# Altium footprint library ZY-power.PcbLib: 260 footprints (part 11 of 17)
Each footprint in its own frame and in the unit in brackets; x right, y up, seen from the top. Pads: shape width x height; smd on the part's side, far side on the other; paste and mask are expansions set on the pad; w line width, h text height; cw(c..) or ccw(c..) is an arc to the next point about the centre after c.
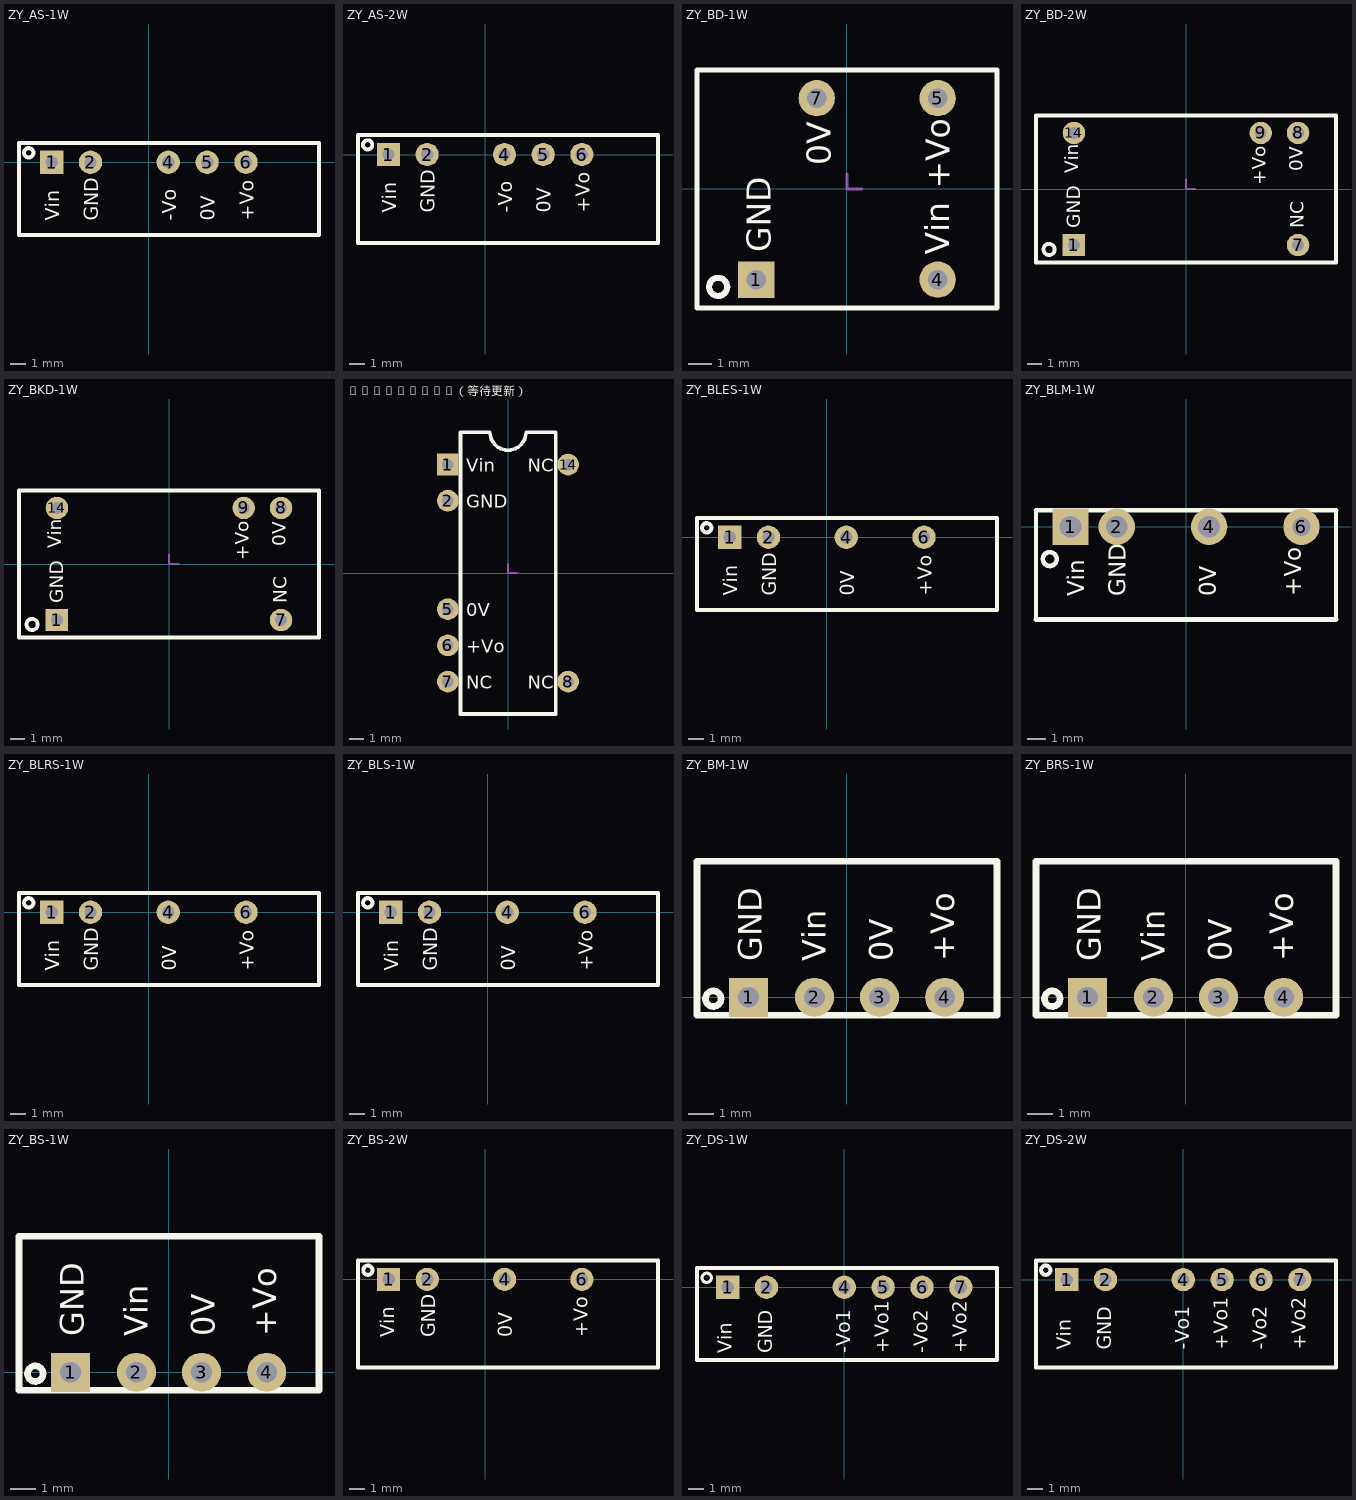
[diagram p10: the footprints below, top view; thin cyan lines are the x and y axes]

## ZY_AS-1W [mil] "定压输入隔离非稳压正、负双输出"
height 393.7
pads (5):
  rect 60x60 hole 32: 1(-250,0)
  round 60 hole 32: 2(-150,0) 4(50,0) 5(150,0) 6(250,0)
Top Overlay:
  circle w10: c-308.86,24.21 r12
  lines w10: -333.86,-187.01 -333.86,49.21 437.8,49.21 437.8,-187.01 -333.86,-187.01
  text "+Vo" at 270,-150 h36
  text "0V" at 170,-150 h36
  text "GND" at -130,-150 h36
  text "Vin" at -230,-150 h36
  text "-Vo" at 70,-150 h36

## ZY_AS-2W [mil] "定压输入隔离非稳压正、负双输出"
height 393.7
pads (5):
  rect 60x60 hole 32: 1(-250,0)
  round 60 hole 32: 2(-150,0) 4(50,0) 5(150,0) 6(250,0)
Top Overlay:
  circle w10: c-303.74,25 r12
  lines w10: 442.91,-228.35 -328.74,-228.35 -328.74,50 -303.74,50 ; 446.85,-228.35 446.85,49.21 ; 446.85,50 -300,50 ; -303.74,50 -300,50 ; -303.74,50 -300,50
  text "+Vo" at 270,-150 h36
  text "0V" at 170,-150 h36
  text "GND" at -130,-150 h36
  text "Vin" at -230,-150 h36
  text "-Vo" at 70,-150 h36

## ZY_BD-1W [mil] "定压输入隔离非稳压单输出"
height 303.15
pads (4):
  rect 60x60 hole 32: 1(-150,-150)
  round 60 hole 32: 4(150,-150) 5(150,150) 7(-50,150)
Top Overlay:
  circle w10: c-213,-162 r15
  lines w8: -248,-197 248.06,-197 248.06,196.7 -248,196.7 -248,-197
  text "0V" at -27,39 h40
  text "+Vo" at 170,0 h40
  text "Vin" at 169,-109 h40
  text "GND" at -126,-105 h40
Mechanical 15:
  lines w5: 0,25 0,0 25,0

## ZY_BD-2W [mil]
height 318.9
pads (5):
  rect 60x60 hole 31.5: 1(-300,-150)
  round 60 hole 31.5: 7(300,-150) 8(300,150) 9(200,150) 14(-300,150)
Top Overlay:
  circle w10: c-366.57,-161.85 r15
  lines w10: -401.57,-196.85 401.57,-196.85 401.57,196.85 -401.57,196.85 -401.57,-196.85
  text "0V" at 312,47 h36
  text "+Vo" at 214,10.66 h36
  text "Vin" at -288,42.37 h36
  text "NC" at 315,-105 h36
  text "GND" at -283,-105 h36
Mechanical 15:
  lines w5: 0,25 0,0 25,0

## ZY_BKD-1W [mil]
height 318.9
pads (5):
  rect 60x60 hole 31.5: 1(-300,-150)
  round 60 hole 31.5: 7(300,-150) 8(300,150) 9(200,150) 14(-300,150)
Top Overlay:
  circle w10: c-366.57,-161.85 r15
  lines w10: -401.57,-196.85 -401.57,196.85 401.57,196.85 401.57,-196.85 -401.57,-196.85
  text "GND" at -283,-105 h36
  text "NC" at 315,-105 h36
  text "Vin" at -288,42.37 h36
  text "+Vo" at 214,10.66 h36
  text "0V" at 312,47 h36
Mechanical 15:
  lines w5: 0,25 0,0 25,0

## ZY_BLD-1W（等待更新） [mil] "定压输入隔离非稳压单输出"
height 216.54
pads (7):
  rect 60x60 hole 32: 1(-166.34,300)
  round 60 hole 32: 2(-166.34,200) 5(-166.34,-100) 6(-166.34,-200) 7(-166.34,-300) 8(166.34,-300) 14(166.34,300)
Top Overlay:
  lines w10: -131.34,-389.76 -131.34,389.76 -50,389.76 ccw(c0,389.76) 0,339.76 ccw(c0,389.76) 50,389.76 131.66,389.76 131.66,-389.76 -131.34,-389.76
  text "NC" at 55,280 h36
  text "NC" at 55,-320 h36
  text "NC" at -115,-320 h36
  text "0V" at -115,-120 h36
  text "+Vo" at -115,-220 h36
  text "GND" at -115,180 h36
  text "Vin" at -115,280 h36
Mechanical 15:
  lines w5: 0,25 0,0 25,0

## ZY_BLES-1W [mil]
height 393.7
pads (4):
  rect 60x60 hole 32: 1(-250,0)
  round 60 hole 32: 2(-150,0) 4(50,0) 6(250,0)
Top Overlay:
  circle w10: c-308.86,24.21 r12
  lines w10: -333.86,-187.01 -333.86,49.21 437.8,49.21 437.8,-187.01 -333.86,-187.01
  text "+Vo" at 270,-150 h36
  text "0V" at 71,-150 h36
  text "GND" at -130,-150 h36
  text "Vin" at -230,-150 h36

## ZY_BLM-1W [mm]
height 7.5
pads (4):
  rect 2x2 hole 1.2: 1(-6.35,0)
  round 2 hole 1.2: 2(-3.81,0) 4(1.27,0)
  round 2 hole 1: 6(6.35,0)
Top Overlay:
  circle w0.254: c-7.493,-1.778 r0.381
  lines w0.245: -8.25,-5.1 -8.25,0.9 ; 8.25,-5.1 8.25,0.9
  lines w0.254: -8.25,-5.1 8.25,-5.1 ; -8.25,0.9 8.25,0.9
  text "+Vo" at 6.35,-3.81 h0.91
  text "0V" at 1.651,-3.81 h0.91
  text "GND" at -3.302,-3.81 h0.91
  text "Vin" at -5.588,-3.81 h0.91

## ZY_BLRS-1W [mil]
height 393.7
pads (4):
  rect 60x60 hole 32: 1(-250,0)
  round 60 hole 32: 2(-150,0) 4(50,0) 6(250,0)
Top Overlay:
  circle w10: c-308.86,24.21 r12
  lines w10: -333.86,-187.01 437.8,-187.01 437.8,49.21 -333.86,49.21 -333.86,-187.01
  text "Vin" at -230,-150 h36
  text "GND" at -130,-150 h36
  text "0V" at 71,-150 h36
  text "+Vo" at 270,-150 h36

## ZY_BLS-1W [mil] "定压输入隔离非稳压单输出"
height 393.7
pads (4):
  rect 60x60 hole 32: 1(-250,0)
  round 60 hole 32: 2(-150,0) 4(50,0) 6(250,0)
Top Overlay:
  circle w10: c-308.86,24.21 r12
  lines w10: -333.86,-187.01 -333.86,49.21 437.8,49.21 437.8,-187.01 -333.86,-187.01
  text "+Vo" at 270,-150 h36
  text "0V" at 71,-150 h36
  text "GND" at -130,-150 h36
  text "Vin" at -230,-150 h36

## ZY_BM-1W [mil]
height 393.7
pads (4):
  rect 60x60 hole 32: 1(-150.5,0)
  round 60 hole 32: 2(-49.5,0) 3(50.5,0) 4(150.5,0)
Top Overlay:
  circle w10: c-204.81,-2.2 r12
  lines w10: -229.81,-27.2 230.81,-27.2 230.81,209.02 -229.81,209.02 -229.81,-27.2
  text "GND" at -130.5,55 h36
  text "Vin" at -32.5,55 h36
  text "0V" at 70.5,55 h36
  text "+Vo" at 165.5,55 h36

## ZY_BRS-1W [mil]
height 393.7
pads (4):
  rect 60x60 hole 32: 1(-150.5,0)
  round 60 hole 32: 2(-49.5,0) 3(50.5,0) 4(150.5,0)
Top Overlay:
  circle w10: c-204.81,-2.2 r12
  lines w10: -229.81,-27.2 -229.81,209.02 230.81,209.02 230.81,-27.2 -229.81,-27.2
  text "+Vo" at 165.5,55 h36
  text "0V" at 70.5,55 h36
  text "Vin" at -32.5,55 h36
  text "GND" at -130.5,55 h36

## ZY_BS-1W [mil] "定压输入隔离非稳压单输出"
height 393.7
pads (4):
  rect 60x60 hole 32: 1(-150.5,0)
  round 60 hole 32: 2(-49.5,0) 3(50.5,0) 4(150.5,0)
Top Overlay:
  circle w10: c-204.81,-2.2 r12
  lines w10: -229.81,-27.2 230.81,-27.2 230.81,209.02 -229.81,209.02 -229.81,-27.2
  text "GND" at -130.5,55 h36
  text "Vin" at -32.5,55 h36
  text "0V" at 70.5,55 h36
  text "+Vo" at 165.5,55 h36

## ZY_BS-2W [mil] "定压输入隔离非稳压单输出"
height 393.7
pads (4):
  rect 60x60 hole 32: 1(-250,0)
  round 60 hole 32: 2(-150,0) 4(50,0) 6(250,0)
Top Overlay:
  circle w10: c-303.74,23.74 r12
  lines w10: 442.91,-228.35 -328.74,-228.35 -328.74,48.74 -329.21,49.21 -299.21,49.21 442.91,49.21 ; 446.85,-228.35 446.85,49.21
  text "+Vo" at 265,-150 h36
  text "0V" at 70,-150 h36
  text "GND" at -130,-150 h36
  text "Vin" at -235,-150 h36

## ZY_DS-1W [mil]
pads (6):
  rect 60x60 hole 32: 1(-300,0)
  round 60 hole 32: 2(-200,0) 4(0,0) 5(100,0) 6(200,0) 7(300,0)
Top Overlay:
  circle w8: c-353.74,24.21 r12
  lines w10: -378.74,-187.01 392.91,-187.01 392.91,49.21 -378.74,49.21 -378.74,-187.01
  text "-Vo1" at 15,-170 h36
  text "Vin" at -290,-170 h36
  text "GND" at -185,-170 h36
  text "+Vo1" at 115,-170 h36
  text "-Vo2" at 215,-170 h36
  text "+Vo2" at 315,-170 h36

## ZY_DS-2W [mil] "定压输入隔离非稳压双输出"
height 393.7
pads (6):
  rect 60x60 hole 32: 1(-300,0)
  round 60 hole 32: 2(-200,0) 4(0,0) 5(100,0) 6(200,0) 7(300,0)
Top Overlay:
  circle w10: c-353.74,24.21 r12
  lines w10: -378.74,-226.38 392.91,-226.38 392.91,49.21 -378.74,49.21 -378.74,-226.38
  text "-Vo1" at 15,-180 h36
  text "Vin" at -290,-180 h36
  text "GND" at -185,-180 h36
  text "+Vo1" at 115,-180 h36
  text "-Vo2" at 215,-180 h36
  text "+Vo2" at 315,-180 h36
